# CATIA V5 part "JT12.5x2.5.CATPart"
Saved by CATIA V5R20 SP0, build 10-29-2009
Part number: JT12.5x2.5
Revision: ANY
Definition: UNKNOWN
Nomenclature: JT12.5x2.5
Source: Unknown
Bounding box of the stored display mesh (mm): x -8.75 to 8.75, y -1.25 to 1.25, z -8.75 to 8.75
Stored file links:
  C:\Users\Utente\Desktop\IO LAVORO\3D X SITO CF\CUMSA\3D files SA\SA 200518\JT12.5x2.5.CATPart
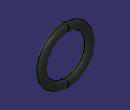
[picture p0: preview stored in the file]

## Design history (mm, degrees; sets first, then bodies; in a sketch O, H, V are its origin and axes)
Body1 "Revolución1" (main body)
  Solid1: solid without history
